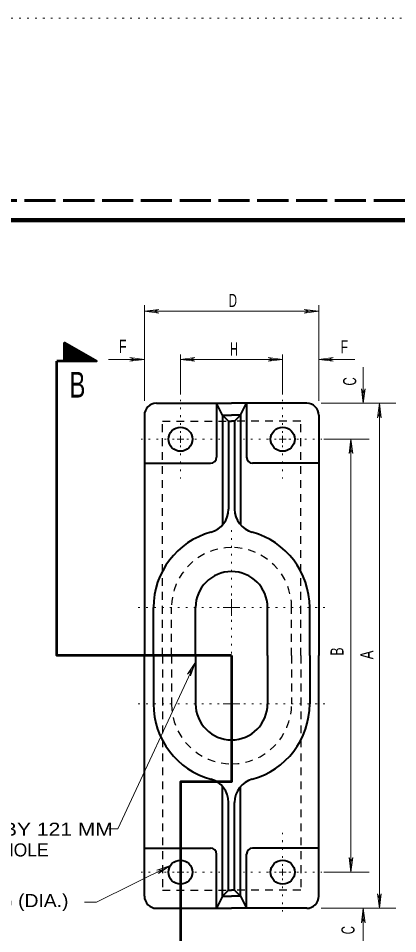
# Model space of a CAD drawing. Extents: x 312583 to 312854, y 144419 to 144597.
# Drawn here: x 312665.1 to 312687.1, y 144543.7 to 144596.8 of the extents above; entities that cross this region are included whole.
import ezdxf
from ezdxf.enums import TextEntityAlignment as Align

# ---------------------------------------------------------------- set-up
doc = ezdxf.new("R2010")
doc.units = 0
doc.header["$LTSCALE"] = 0.3
for name, pattern in [('DOTTED', [1.5, 0.3, -1.2]), ('LONG_DASHED', [7.5, 6, -1.5]), ('SHORT_DASHED', [2.7, 1.5, -1.2])]:
    doc.linetypes.add(name, pattern=pattern)
for name, color, linetype, lineweight in [('1', 7, 'Continuous', 13), ('62', 7, 'DOTTED', 13), ('63', 7, 'LONG_DASHED', 60)]:
    doc.layers.add(name, color=color, linetype=linetype, lineweight=lineweight)

msp = doc.modelspace()

# ---------------------------------------------------------------- linework, layer by layer
at = {"layer": '1'}
for p, q in [((312672.3992, 144574.6206), (312672.3992, 144580.1559)), ((312672.3992, 144579.8033), (312673.2426, 144579.9106)), ((312672.3992, 144579.8033), (312682.5116, 144579.8033)), ((312672.3992, 144579.8033), (312673.2426, 144579.7036)), ((312673.2426, 144579.9106), (312672.9742, 144579.8033)), ((312673.2426, 144579.7036), (312672.9742, 144579.8033)), ((312681.6682, 144579.9106), (312681.9366, 144579.8033)), ((312682.5116, 144579.8033), (312681.6682, 144579.9106)), ((312681.6682, 144579.7036), (312681.9366, 144579.8033)), ((312682.5116, 144579.8033), (312681.6682, 144579.7036)), ((312682.5116, 144574.6206), (312682.5116, 144580.1559)), ((312671.5636, 144577.1199), (312671.8319, 144577.0203)), ((312672.3992, 144577.0203), (312671.5636, 144577.1199)), ((312674.4922, 144574.9886), (312674.4922, 144577.2963)), ((312674.4922, 144577.0203), (312675.3356, 144577.1199)), ((312675.3356, 144577.1199), (312675.0672, 144577.0203)), ((312679.5829, 144577.1199), (312679.8512, 144577.0203)), ((312680.4186, 144577.0203), (312679.5829, 144577.1199)), ((312680.4186, 144574.9886), (312680.4186, 144577.2963)), ((312682.5116, 144577.0203), (312683.3472, 144577.1199)), ((312683.3472, 144577.1199), (312683.0789, 144577.0203)), ((312672.3992, 144577.0203), (312670.3139, 144577.0203)), ((312671.5636, 144576.9129), (312671.8319, 144577.0203)), ((312672.3992, 144577.0203), (312671.5636, 144576.9129)), ((312680.4186, 144577.0203), (312674.4922, 144577.0203)), ((312674.4922, 144577.0203), (312675.3356, 144576.9129)), ((312675.3356, 144576.9129), (312675.0672, 144577.0203)), ((312679.5829, 144576.9129), (312679.8512, 144577.0203)), ((312680.4186, 144577.0203), (312679.5829, 144576.9129)), ((312682.5116, 144577.0203), (312684.6046, 144577.0203)), ((312682.5116, 144577.0203), (312683.3472, 144576.9129)), ((312683.3472, 144576.9129), (312683.0789, 144577.0203)), ((312685.0876, 144574.4826), (312685.0876, 144576.5756)), ((312684.9879, 144575.3183), (312685.0876, 144575.0499)), ((312685.0876, 144574.4826), (312684.9879, 144575.3183)), ((312685.1949, 144575.3183), (312685.0876, 144575.0499)), ((312685.0876, 144574.4826), (312685.1949, 144575.3183)), ((312686.9724, 144574.4826), (312682.6496, 144574.4826)), ((312686.0356, 144574.4826), (312685.9283, 144573.6393)), ((312686.0356, 144559.8469), (312686.0356, 144574.4826)), ((312686.0356, 144574.4826), (312686.1353, 144573.6393)), ((312685.9283, 144573.6393), (312686.0356, 144573.9076)), ((312686.1353, 144573.6393), (312686.0356, 144573.9076)), ((312674.4922, 144572.3896), (312674.2929, 144572.3896)), ((312674.4922, 144572.3896), (312674.4922, 144572.5889)), ((312674.4922, 144572.3896), (312674.6916, 144572.3896)), ((312674.4922, 144572.3896), (312674.4922, 144572.1903)), ((312680.4186, 144572.3896), (312680.2192, 144572.3896)), ((312680.4186, 144572.3896), (312680.4186, 144572.5889)), ((312680.4186, 144572.3896), (312680.4186, 144572.1903)), ((312680.4186, 144572.3896), (312680.6179, 144572.3896)), ((312685.4402, 144572.3896), (312682.8029, 144572.3896)), ((312684.3789, 144572.3896), (312684.2792, 144571.5539)), ((312684.3789, 144559.8469), (312684.3789, 144572.3896)), ((312684.3789, 144572.3896), (312684.4862, 144571.5539)), ((312684.2792, 144571.5539), (312684.3789, 144571.8223)), ((312684.4862, 144571.5539), (312684.3789, 144571.8223)), ((312677.4592, 144562.6299), (312677.4592, 144563.1129)), ((312677.4592, 144562.6299), (312676.9762, 144562.6299)), ((312677.4592, 144562.6299), (312677.9346, 144562.6299)), ((312677.4592, 144562.6299), (312677.4592, 144562.1546)), ((312684.3789, 144559.8469), (312684.3789, 144547.2966)), ((312686.0356, 144559.8469), (312686.0356, 144545.2113)), ((312675.3662, 144559.4738), (312670.8682, 144549.81)), ((312675.3662, 144559.4738), (312674.8959, 144558.7676)), ((312675.3662, 144559.4738), (312675.0835, 144558.6688)), ((312674.8959, 144558.7676), (312675.1157, 144558.962)), ((312675.0835, 144558.6688), (312675.1157, 144558.962)), ((312677.4592, 144557.0563), (312677.4592, 144557.5316)), ((312677.4592, 144557.0563), (312676.9762, 144557.0563)), ((312677.4592, 144557.0563), (312677.9346, 144557.0563)), ((312677.4592, 144557.0563), (312677.4592, 144556.5809)), ((312670.8682, 144549.81), (312670.3397, 144549.81)), ((312684.2792, 144548.1399), (312684.3789, 144547.8716)), ((312684.3789, 144547.2966), (312684.2792, 144548.1399)), ((312684.4862, 144548.1399), (312684.3789, 144547.8716)), ((312684.3789, 144547.2966), (312684.4862, 144548.1399)), ((312673.9179, 144547.6932), (312673.1195, 144547.4089)), ((312673.1195, 144547.4089), (312673.4099, 144547.4335)), ((312673.9179, 144547.6932), (312673.2109, 144547.2239)), ((312673.2109, 144547.2239), (312673.4099, 144547.4335)), ((312674.4922, 144547.2966), (312674.4922, 144547.4959)), ((312680.4186, 144547.2966), (312680.4186, 144547.4959)), ((312674.4922, 144547.2966), (312674.2929, 144547.2966)), ((312674.4922, 144547.2966), (312674.6916, 144547.2966)), ((312674.4922, 144547.2966), (312674.4922, 144547.1049)), ((312680.4186, 144547.2966), (312680.2192, 144547.2966)), ((312680.4186, 144547.2966), (312680.6179, 144547.2966)), ((312680.4186, 144547.2966), (312680.4186, 144547.1049)), ((312685.4402, 144547.2966), (312682.8029, 144547.2966)), ((312685.9283, 144546.0469), (312686.0356, 144545.7786)), ((312686.0356, 144545.2113), (312685.9283, 144546.0469)), ((312686.1353, 144546.0469), (312686.0356, 144545.7786)), ((312686.0356, 144545.2113), (312686.1353, 144546.0469)), ((312686.9724, 144545.2113), (312682.6496, 144545.2113)), ((312685.0876, 144545.2113), (312684.9879, 144544.3679)), ((312685.0876, 144545.2113), (312685.0876, 144543.1183)), ((312685.0876, 144545.2113), (312685.1949, 144544.3679)), ((312684.9879, 144544.3679), (312685.0876, 144544.6363)), ((312685.1949, 144544.3679), (312685.0876, 144544.6363))]:
    msp.add_line(p, q, dxfattribs=at)
at = {"layer": '1', "lineweight": 35}
for p, q in [((312667.7762, 144577.9556), (312667.7916, 144577.9709)), ((312667.7762, 144577.9096), (312667.8146, 144577.9633)), ((312667.7762, 144577.8636), (312667.8299, 144577.9479)), ((312667.7762, 144577.8176), (312667.8529, 144577.9326)), ((312667.7762, 144577.7639), (312667.8682, 144577.9249)), ((312667.7762, 144577.7256), (312667.8836, 144577.9096)), ((312667.7762, 144577.6796), (312667.9066, 144577.9019)), ((312667.7762, 144577.6336), (312667.9296, 144577.8943)), ((312667.7762, 144577.5876), (312667.9449, 144577.8789)), ((312667.7762, 144577.5416), (312667.9756, 144577.8713)), ((312667.7762, 144577.4879), (312667.9909, 144577.8636)), ((312667.7762, 144577.4419), (312668.0139, 144577.8483)), ((312667.7762, 144577.4036), (312668.0369, 144577.8406)), ((312667.7762, 144577.3499), (312668.0522, 144577.8253)), ((312667.7762, 144577.3039), (312668.0752, 144577.8176)), ((312667.7762, 144577.2579), (312668.0829, 144577.8023)), ((312667.7762, 144577.2043), (312668.1059, 144577.7869)), ((312667.7762, 144577.1659), (312668.1289, 144577.7793)), ((312667.7762, 144577.1199), (312668.1442, 144577.7639)), ((312667.7762, 144577.0739), (312668.1672, 144577.7486)), ((312667.7762, 144577.0203), (312668.1902, 144577.7409)), ((312667.7762, 144576.9819), (312668.2056, 144577.7256)), ((312667.7762, 144576.9283), (312668.2362, 144577.7179)), ((312667.7916, 144576.9129), (312668.2516, 144577.7026)), ((312667.8222, 144576.9129), (312668.2746, 144577.6949)), ((312667.8529, 144576.9129), (312668.2976, 144577.6796)), ((312667.8682, 144576.9129), (312668.3129, 144577.6796)), ((312667.8989, 144576.9129), (312668.3282, 144577.6566)), ((312667.9219, 144576.9206), (312668.3512, 144577.6566)), ((312667.9526, 144576.9206), (312668.3742, 144577.6336)), ((312667.9756, 144576.9129), (312668.3896, 144577.6336)), ((312668.0062, 144576.9129), (312668.4126, 144577.6183)), ((312668.0369, 144576.9129), (312668.4279, 144577.6029)), ((312668.0599, 144576.9129), (312668.4509, 144577.5953)), ((312668.0829, 144576.9129), (312668.4739, 144577.5799)), ((312668.1136, 144576.9129), (312668.4969, 144577.5646)), ((312668.1366, 144576.9129), (312668.5122, 144577.5569)), ((312668.1672, 144576.9206), (312668.5352, 144577.5416)), ((312668.1979, 144576.9129), (312668.5582, 144577.5339)), ((312668.2209, 144576.9129), (312668.5736, 144577.5186)), ((312668.2439, 144576.9129), (312668.5966, 144577.5109)), ((312668.2746, 144576.9129), (312668.6196, 144577.4956)), ((312668.3052, 144576.9129), (312668.6272, 144577.4879)), ((312668.3282, 144576.9129), (312668.6502, 144577.4726)), ((312668.3512, 144576.9129), (312668.6732, 144577.4649)), ((312668.3819, 144576.9129), (312668.6886, 144577.4496)), ((312668.4049, 144576.9206), (312668.7192, 144577.4419)), ((312668.4356, 144576.9129), (312668.7346, 144577.4343)), ((312668.4586, 144576.9129), (312668.7576, 144577.4113)), ((312668.4892, 144576.9129), (312668.7806, 144577.4113)), ((312668.5199, 144576.9129), (312668.7959, 144577.3883)), ((312668.5429, 144576.9129), (312668.8189, 144577.3883)), ((312668.5736, 144576.9129), (312668.8419, 144577.3729)), ((312668.5966, 144576.9129), (312668.8496, 144577.3653)), ((312668.6196, 144576.9129), (312668.8726, 144577.3499)), ((312668.6502, 144576.9129), (312668.8956, 144577.3423)), ((312668.6809, 144576.9129), (312668.9109, 144577.3269)), ((312668.7039, 144576.9129), (312668.9339, 144577.3193)), ((312668.7269, 144576.9129), (312668.9569, 144577.3039)), ((312668.7576, 144576.9129), (312668.9799, 144577.2963)), ((312668.7882, 144576.9129), (312668.9952, 144577.2809)), ((312668.8189, 144576.9129), (312669.0182, 144577.2656)), ((312668.8419, 144576.9129), (312669.0412, 144577.2579)), ((312668.8649, 144576.9129), (312669.0566, 144577.2426)), ((312668.8879, 144576.9129), (312669.0796, 144577.2273)), ((312668.9186, 144576.9129), (312669.0949, 144577.2196)), ((312668.9416, 144576.9129), (312669.1102, 144577.2043)), ((312668.9722, 144576.9129), (312669.1332, 144577.1966)), ((312669.0029, 144576.9129), (312669.1562, 144577.1889)), ((312669.0259, 144576.9129), (312669.1716, 144577.1736)), ((312669.0566, 144576.9129), (312669.2022, 144577.1659)), ((312669.0796, 144576.9129), (312669.2176, 144577.1583)), ((312669.1102, 144576.9129), (312669.2406, 144577.1429)), ((312669.1332, 144576.9129), (312669.2636, 144577.1353)), ((312669.1562, 144576.9129), (312669.2789, 144577.1199)), ((312669.1869, 144576.9129), (312669.3019, 144577.1123)), ((312669.2099, 144576.9129), (312669.3249, 144577.0969)), ((312669.2406, 144576.9129), (312669.3326, 144577.0816)), ((312669.2712, 144576.9129), (312669.3556, 144577.0739)), ((312669.3019, 144576.9129), (312669.3786, 144577.0586)), ((312669.3249, 144576.9129), (312669.3939, 144577.0433)), ((312669.3556, 144576.9129), (312669.4169, 144577.0356)), ((312669.3709, 144576.9129), (312669.4399, 144577.0203)), ((312669.3939, 144576.9129), (312669.4629, 144577.0126)), ((312669.4246, 144576.9129), (312669.4782, 144576.9973)), ((312669.4552, 144576.9129), (312669.5012, 144576.9896)), ((312669.4859, 144576.9129), (312669.5242, 144576.9743)), ((312669.5089, 144576.9129), (312669.5396, 144576.9666)), ((312669.5396, 144576.9129), (312669.5549, 144576.9513)), ((312669.5549, 144576.9129), (312669.5779, 144576.9436)), ((312669.5856, 144576.9129), (312669.6009, 144576.9283)), ((312669.6162, 144576.9129), (312669.6162, 144576.9206))]:
    msp.add_line(p, q, dxfattribs=at)
at = {"layer": '1', "lineweight": 53}
for p, q in [((312667.3162, 144574.5899), (312667.3162, 144576.9129)), ((312667.7762, 144576.9129), (312667.3162, 144576.9129)), ((312674.4922, 144543.7776), (312674.4922, 144540.9409))]:
    msp.add_line(p, q, dxfattribs=at)
at = {"layer": '1', "lineweight": 40}
for p, q in [((312673.0969, 144574.4826), (312677.4592, 144574.4826)), ((312676.5852, 144574.4826), (312676.5852, 144571.3469)), ((312676.9302, 144573.7849), (312676.5852, 144574.4826)), ((312681.8139, 144574.4826), (312677.4592, 144574.4826)), ((312677.9806, 144573.7849), (312678.3256, 144574.4826)), ((312678.3256, 144574.4826), (312678.3256, 144571.3469)), ((312672.3992, 144573.7849), (312672.3992, 144559.8469)), ((312676.9302, 144573.7849), (312677.4592, 144573.7849)), ((312676.9302, 144573.7849), (312676.9302, 144567.4216)), ((312677.2829, 144573.4323), (312677.2829, 144568.3416)), ((312677.9806, 144573.7849), (312677.4592, 144573.7849)), ((312677.6279, 144573.4323), (312677.6279, 144568.3416)), ((312677.9806, 144573.7849), (312677.9806, 144567.4216)), ((312682.5116, 144573.7849), (312682.5116, 144559.8469)), ((312672.3992, 144570.9943), (312676.2326, 144570.9943)), ((312682.5116, 144570.9943), (312678.6782, 144570.9943)), ((312672.9282, 144559.8469), (312672.9282, 144562.6299)), ((312675.3662, 144559.8469), (312675.3662, 144562.6299)), ((312679.5446, 144559.8469), (312679.5446, 144562.6299)), ((312681.9902, 144559.8469), (312681.9902, 144562.6299)), ((312672.3992, 144545.9089), (312672.3992, 144559.8469)), ((312672.9282, 144559.8469), (312672.9282, 144557.0563)), ((312675.3662, 144559.8469), (312675.3662, 144557.0563)), ((312679.5446, 144559.8469), (312679.5446, 144557.0563)), ((312681.9902, 144559.8469), (312681.9902, 144557.0563)), ((312682.5116, 144545.9089), (312682.5116, 144559.8469)), ((312676.9302, 144545.9089), (312676.9302, 144552.2723)), ((312677.9806, 144545.9089), (312677.9806, 144552.2723)), ((312677.2829, 144546.2539), (312677.2829, 144551.3446)), ((312677.6279, 144546.2539), (312677.6279, 144551.3446)), ((312672.3992, 144548.6919), (312676.2326, 144548.6919)), ((312682.5116, 144548.6919), (312678.6782, 144548.6919)), ((312676.5852, 144545.2113), (312676.5852, 144548.3469)), ((312678.3256, 144545.2113), (312678.3256, 144548.3469)), ((312676.9302, 144545.9089), (312676.5852, 144545.2113)), ((312676.9302, 144545.9089), (312677.4592, 144545.9089)), ((312677.9806, 144545.9089), (312677.4592, 144545.9089)), ((312677.9806, 144545.9089), (312678.3256, 144545.2113)), ((312673.0969, 144545.2113), (312677.4592, 144545.2113)), ((312681.8139, 144545.2113), (312677.4592, 144545.2113))]:
    msp.add_line(p, q, dxfattribs=at)
at = {"layer": '1', "linetype": 'DOTTED'}
for p, q in [((312674.4922, 144572.7576), (312674.4922, 144574.6666)), ((312680.4186, 144572.7576), (312680.4186, 144574.6666)), ((312674.1242, 144572.3896), (312672.2152, 144572.3896)), ((312674.8602, 144572.3896), (312676.7692, 144572.3896)), ((312680.0506, 144572.3896), (312678.1416, 144572.3896)), ((312680.7866, 144572.3896), (312682.6956, 144572.3896)), ((312674.4922, 144572.0216), (312674.4922, 144570.1126)), ((312680.4186, 144572.0216), (312680.4186, 144570.1126)), ((312677.4592, 144563.3429), (312677.4592, 144567.2146)), ((312676.7462, 144562.6299), (312672.0159, 144562.6299)), ((312678.1722, 144562.6299), (312682.9792, 144562.6299)), ((312677.4592, 144561.9169), (312677.4592, 144559.8469)), ((312677.4592, 144557.7693), (312677.4592, 144559.8469)), ((312676.7462, 144557.0563), (312672.0159, 144557.0563)), ((312678.1722, 144557.0563), (312682.9792, 144557.0563)), ((312677.4592, 144556.3433), (312677.4592, 144552.4716)), ((312674.4922, 144547.6646), (312674.4922, 144549.5736)), ((312680.4186, 144547.6646), (312680.4186, 144549.5736)), ((312674.1242, 144547.2966), (312672.2152, 144547.2966)), ((312674.4922, 144546.9286), (312674.4922, 144545.0196)), ((312674.8602, 144547.2966), (312676.7692, 144547.2966)), ((312680.0506, 144547.2966), (312678.1416, 144547.2966)), ((312680.4186, 144546.9286), (312680.4186, 144545.0196)), ((312680.7866, 144547.2966), (312682.6956, 144547.2966))]:
    msp.add_line(p, q, dxfattribs=at)
at = {"layer": '1', "linetype": 'SHORT_DASHED', "lineweight": 25}
for p, q in [((312673.9709, 144559.8469), (312673.9709, 144562.6299)), ((312680.9399, 144559.8469), (312680.9399, 144562.6299)), ((312673.9709, 144559.8469), (312673.9709, 144557.0563)), ((312680.9399, 144559.8469), (312680.9399, 144557.0563))]:
    msp.add_line(p, q, dxfattribs=at)
at = {"layer": '1', "lineweight": 158}
msp.add_lwpolyline([(312616.5, 144423.1446), (312616.5, 144585.0846), (312849, 144585.0846)], dxfattribs=at)
at = {"layer": '1', "lineweight": 53}
msp.add_lwpolyline([(312667.7762, 144576.9129), (312667.7762, 144577.9863), (312669.6316, 144576.9129)], close=True, dxfattribs=at)
for points in [[(312677.4592, 144559.8469), (312667.3162, 144559.8469), (312667.3162, 144574.5899)], [(312677.4592, 144559.8469), (312677.4592, 144552.5406), (312674.4922, 144552.5406), (312674.4922, 144543.7776)]]:
    msp.add_lwpolyline(points, dxfattribs=at)
at = {"layer": '1', "linetype": 'SHORT_DASHED', "lineweight": 25}
for points in [[(312673.4496, 144559.8469), (312673.4496, 144573.4323), (312677.4592, 144573.4323)], [(312681.4689, 144559.8469), (312681.4689, 144573.4323), (312677.4592, 144573.4323)], [(312673.4496, 144559.8469), (312673.4496, 144546.2539), (312677.4592, 144546.2539)], [(312681.4689, 144559.8469), (312681.4689, 144546.2539), (312677.4592, 144546.2539)]]:
    msp.add_lwpolyline(points, dxfattribs=at)
at = {"layer": '1', "lineweight": 40}
for points in [[(312676.9302, 144573.7849), (312677.2829, 144573.4323), (312677.4592, 144573.4323)], [(312677.9806, 144573.7849), (312677.6279, 144573.4323), (312677.4592, 144573.4323)], [(312676.9302, 144545.9089), (312677.2829, 144546.2539), (312677.4592, 144546.2539)], [(312677.9806, 144545.9089), (312677.6279, 144546.2539), (312677.4592, 144546.2539)]]:
    msp.add_lwpolyline(points, dxfattribs=at)
at = {"layer": '1'}
msp.add_lwpolyline([(312673.9179, 144547.6932), (312669.6281, 144545.5543), (312668.9304, 144545.5543)], dxfattribs=at)
at = {"layer": '1', "lineweight": 40}
for centre in [(312674.4929, 144572.3903), (312680.42, 144572.3903), (312674.4929, 144547.2994), (312680.42, 144547.2994)]:
    msp.add_circle(centre, 0.697, dxfattribs=at)
for centre, radius, start, end in [((312673.099, 144573.7842), 0.697, 90, 180), ((312681.8139, 144573.7842), 0.697, 0, 90), ((312676.2354, 144571.3448), 0.3485, 270, 0), ((312678.6775, 144571.3448), 0.3485, 180, 270), ((312675.8897, 144568.346), 1.3939, 285.3355, 0), ((312679.0232, 144568.346), 1.3939, 180, 254.6645), ((312677.4564, 144562.6327), 4.5303, 105.33548, 180), ((312677.4564, 144562.6327), 4.5303, 0, 74.66452), ((312677.4564, 144562.6327), 2.0909, 90, 180), ((312677.4564, 144562.6327), 2.0909, 0, 90), ((312677.4564, 144557.057), 4.5303, 180, 254.66452), ((312677.4564, 144557.057), 2.0909, 180, 270), ((312677.4564, 144557.057), 2.0909, 270, 0), ((312677.4564, 144557.057), 4.5303, 285.33548, 0), ((312675.8897, 144551.3437), 1.3939, 0, 74.6645), ((312679.0232, 144551.3437), 1.3939, 105.3355, 180), ((312676.2354, 144548.3448), 0.3485, 0, 90), ((312678.6775, 144548.3448), 0.3485, 90, 180), ((312673.099, 144545.9054), 0.697, 180, 270), ((312681.8139, 144545.9054), 0.697, 270, 0)]:
    msp.add_arc(centre, radius, start, end, dxfattribs=at)
at = {"layer": '1', "linetype": 'SHORT_DASHED', "lineweight": 25}
for centre, start, end in [((312677.4564, 144562.6327), 90, 180), ((312677.4564, 144562.6327), 0, 90), ((312677.4564, 144557.057), 180, 270), ((312677.4564, 144557.057), 270, 0)]:
    msp.add_arc(centre, 3.4848, start, end, dxfattribs=at)
at = {"layer": '62'}
msp.add_line((312601.2, 144596.7846), (312853.5, 144596.7846), dxfattribs=at)
at = {"layer": '63'}
msp.add_line((312851.75, 144586.2246), (312583.526, 144586.2246), dxfattribs=at)

# ---------------------------------------------------------------- texts
at = {"layer": '1'}
for s, width, p in [('D', 0.65, (312677.2931, 144580.0553)), ('F', 0.7, (312670.9287, 144577.3969)), ('H', 0.6, (312677.3758, 144577.2368)), ('F', 0.7, (312683.7763, 144577.3615)), ('44 MM BY 121 MM', 1.2, (312660.1341, 144549.4066)), ('G (DIA.)', 1.1, (312663.9001, 144545.2716))]:
    msp.add_text(s, height=0.76, dxfattribs=dict(at, width=width)).set_placement(p)
at = {"layer": '1', "width": 0.7}
msp.add_text('B', height=1.489, dxfattribs=at).set_placement((312668.516, 144574.8046), align=Align.CENTER)
at = {"layer": '1'}
for s, width, p in [('C', 0.65, (312684.6859, 144575.5028)), ('B', 0.7, (312683.9501, 144559.8484)), ('A', 0.75, (312685.6777, 144559.6343)), ('C', 0.65, (312684.5879, 144543.7004))]:
    msp.add_text(s, height=0.76, rotation=90, dxfattribs=dict(at, width=width)).set_placement(p)
msp.add_text('CORED HOLE', height=0.76, dxfattribs=at).set_placement((312660.1341, 144548.2096))

doc.saveas('drawing.dxf')
